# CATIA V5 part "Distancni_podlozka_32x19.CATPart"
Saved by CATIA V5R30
Part number: Distancni_podlozka_32x19
Definition: EH 6200_32x19
Nomenclature: EH 6200_32x19
Source: Unknown
Description: PART--DESC
Bounding box of the stored display mesh (mm): x -16 to 16, y -15.99 to 15.99, z 15.7 to 41.2
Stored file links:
  E:\Bakalarka\Model\Forma_v7\Distancni_podlozka_32x19.CATPart
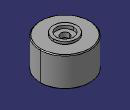
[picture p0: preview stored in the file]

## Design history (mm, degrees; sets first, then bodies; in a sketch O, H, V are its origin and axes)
Body1 "MANIFOLD_SOLID_BREP #3754" (main body)
  Solid1: solid without history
